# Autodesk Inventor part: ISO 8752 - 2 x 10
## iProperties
Created: 2004-10
Part Number: ISO 8752 - 2 x 10
Material: Standard
Catalog Web Link: file:///C:/Programme/Autodesk/Inventor 5.3/Content/Din/index.htm?doNavigateId=75DC2E92-CB48-11D4-A9FB-0080AD303E0A|0557C0AEB16611D4BA6900C04F798F98|true
Description: Spannstift
Document SubType Name: Standard Catalog Part
Standard: ISO 8752 - 2 x 10
Designer: Ulrich
Control State: 0
Master: False
Checked Out: False
Shininess: 20.0
Angle Display Precision: 2
Document Length Units: 11269
Document Angle Units: 11279
Document Time Units: 11290
Document Mass Units: 11283
Document Length Units Precision: 3
Document Angle Units Precision: 2
Compacted: True
KLASSIFIKATION: 31163201 un/spsc
HERSTELLER: DIN Normsystem
Density: 0.0
Volumn: 0.0
Area: 0.0
PropertySet Name: Model Information
Author: Ulrich
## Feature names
1. Basis1
